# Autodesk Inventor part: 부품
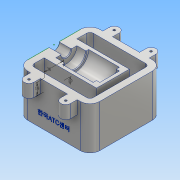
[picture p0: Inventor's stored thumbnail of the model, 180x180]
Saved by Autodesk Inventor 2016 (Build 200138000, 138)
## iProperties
Created: 2018-01
Part Number: 부품
Material: 알루미늄 6061
Document SubType Name: Modeling
Designer: Administrator
Density: 2.7 g/cm^3
Appearance: 알루미늄 - 평지
Mass: 1035.04 g
Surface Area: 788.468 cm^2
Volume: 383.348 cm^3
Author: Administrator
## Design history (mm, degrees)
sketch "스케치1"
  geometry: L1 (-55, 55)-(55, 55); L2 (55, 55)-(55, -55); L3 (55, -55)-(-55, -55); L4 (-55, -55)-(-55, 55); L5 (-55, 55)-(55, -55); L6 (55, 55)-(-55, -55); 1 further point
  constraints: 12 end point, 2 midpoint, 2 parallel, 1 horizontal, 1 perpendicular
  dimensions: "d0" = 110 distance of L1.start L1.end; "d1" = 110 distance of L1.end L2.end
extrude "돌출1" new body sketch "스케치1" distance "d2" = 65; taper "d3" = 0 deg
sketch "스케치2"
  geometry: L1 (55, 55)-(-55, 55) reference; L2 (-55, 55)-(-55, -55) reference; L3 (-55, -55)-(55, -55) reference; L4 (55, -55)-(55, 55) reference; L5 (-45, 45)-(-45, 25); L6 (-45, 25)-(35, 25); L7 (35, 25)-(35, -25); L8 (35, -25)-(-45, -25); L9 (-45, -25)-(-45, -45); L10 (-45, -45)-(45, -45); L11 (45, -45)-(45, 45); L12 (45, 45)-(-45, 45); 1 further point
  constraints: 16 end point, 6 perpendicular, 2 point on line, 1 vertical
  dimensions: "d4" = 30 distance between parallel lines of L1 L6; "d5" = 10 distance between parallel lines of L2 L5; "d6" = 20 distance between parallel lines of L4 L7; "d7" = 10 distance between parallel lines of L4 L11; "d8" = 10 distance between parallel lines of L1 L12; "d9" = 10 distance between parallel lines of L3 L10; "d10" = 30 distance between parallel lines of L3 L8
extrude "돌출2" cut sketch "스케치2" stored distance "d11" = 65; taper "d12" = 0 deg
sketch "스케치3"
  geometry: L1 (55, 55)-(-55, 55) reference; L2 (-55, 55)-(-55, -55) reference; L3 (-35.5, 65)-(-20.5, 65); L4 (-20.5, 65)-(-20.5, 55); L5 (-20.5, 55)-(-35.5, 55); L6 (-35.5, 55)-(-35.5, 65); L7 (-35.5, 65)-(-20.5, 55); L8 (-20.5, 65)-(-35.5, 55); L9 (0, 0)-(0, 92.754); L10 (20.5, 55)-(35.5, 55); L11 (35.5, 65)-(20.5, 65); L12 (20.5, 65)-(20.5, 55); L13 (35.5, 65)-(20.5, 55); L14 (20.5, 65)-(35.5, 55); L15 (35.5, 55)-(35.5, 65); A1 r 7.5 centre (-28, 65) between (-20.5, 65) and (-35.5, 65); A2 r 7.5 centre (28, 65) between (35.5, 65) and (20.5, 65); 2 further points
  constraints: 26 end point, 6 symmetric about line, 5 midpoint, 4 point on circle, 2 centre point, 2 parallel, 1 horizontal, 1 perpendicular, 1 point on line, 1 vertical, 1 other
  dimensions: "d13" = 27 distance from line of L2 A1.centre; "d14" = 7.5 radius of A1; "d15" = 10 distance between parallel lines of L1 L3
extrude "돌출3" join sketch "스케치3" distance "d16" = 20; taper "d17" = 0 deg
fillet "모깎기1" dims "d27" = 15
fillet "모깎기2" dims "d28" = 5
sketch "스케치8"
  geometry: L1 (45, -25)-(-35, -25); L2 (-35, -25)-(-35, 25); L3 (-35, 25)-(45, 25); L4 (45, 25)-(45, -25); 1 further point
  constraints: 8 end point, 2 parallel, 1 horizontal, 1 perpendicular
extrude "돌출4" cut sketch "스케치8" stored distance "d33" = 45; taper "d34" = 0 deg
sketch "스케치11"
  geometry: L1 (-55, -40)-(-55, 40) reference; L2 (-55, 25)-(35, 25); L3 (35, 25)-(35, -25); L4 (35, -25)-(-55, -25); L5 (-55, -25)-(-55, 25); 2 further points
  constraints: 8 end point, 2 parallel, 1 horizontal, 1 horizontal alignment, 1 midpoint, 1 perpendicular, 1 point on line
  dimensions: "d45" = 90 distance of L2.start L2.end; "d46" = 50 distance of L2.end L3.end
extrude "돌출5" join sketch "스케치11" stored distance "d47" = 40; taper "d48" = 0 deg
sketch "스케치12"
  geometry: L1 (-55, 40)-(-55, -40) reference; L2 (-55, 0)-(70.588, 0); L3 (-55, 0)-(-55, 7.5); L4 (-55, 7.5)-(-36, 7.5); L5 (-36, 7.5)-(-36, 16); L6 (-36, 16)-(-22, 16); L7 (-22, 16)-(-22, 20); L8 (-22, 20)-(25, 20); L9 (25, 20)-(25, 15); L10 (25, 15)-(30, 15); L11 (30, 15)-(30, 0); 1 further point
  constraints: 20 end point, 7 perpendicular, 2 horizontal, 2 point on line, 1 midpoint
  dimensions: "d49" = 15 diameter of L4 L2; "d50" = 19 distance of L3.end L4.end; "d51" = 14 distance of L5.end L6.end; "d52" = 32 diameter of L6 L2; "d53" = 40 diameter of L8 L2; "d54" = 30 diameter of L10 L2; "d55" = 47 distance of L7.end L8.end; "d56" = 5 distance of L9.end L10.end
revolve "회전2" sketch "스케치12" stored, may be unused: angle "d57" = 180 deg
sketch "스케치15"
  geometry: A1 r 7.5 centre (-28, -65) between (-35.5, -65) and (-20.5, -65) reference; A2 r 7.5 centre (28, -65) between (20.5, -65) and (35.5, -65) reference; A3 r 7.5 centre (28, 65) between (35.5, 65) and (20.5, 65) reference; A4 r 7.5 centre (-28, 65) between (-20.5, 65) and (-35.5, 65) reference; 5 further points
  constraints: 4 coincident
hole "구멍1" sketch "스케치15" at (-28, -65), (28, -65), (28, 65), (-28, 65) diameter "d66" = 3.242; stored, may be unused: countersink angle "d70" = 90 deg, drill point angle "d72" = 118 deg; dims "d67" = 9, "d68" = 4, "d69" = 2, "d71" = 11
sketch "스케치16" dims "d0" = 110, "d1" = 110
  geometry: L1 (60.5, -65)-(-19.5, -65) reference; L2 (-34.5, 0)-(-34.5, -65) reference; 2 further points
  constraints: 1 other
  dimensions: "d77" = 20 distance from line of L1 point (20.5, -45); "d78" = 55 distance from line of L2 point (20.5, -45)
feature "엠보싱1" sketch "스케치16" dims "d79" = 0.5, "d80" = 0
fillet "모깎기7" dims "d81" = 1
chamfer "모따기1" distance "d82" = 1; stored, may be unused: second distance "d83" = 2, angle "d84" = 45 deg
sketch "스케치19"
  geometry: L1 (-35, 65)-(-35, 0) reference; L2 (-35, 30)-(45, 8.564); L3 (45, 8.564)-(45, 0); L4 (40, 0)-(-40, 0) reference; L5 (55, 0)-(55, 65) reference; L6 (-35, 30)-(-35, 0); L7 (-32, 0)-(-32, 65) reference; L8 (45, 0)-(-35, 0); 1 further point
  constraints: 8 end point, 2 point on line, 1 collinear, 1 parallel, 1 vertical
  dimensions: "d85" = 105 deg angle of L3 L2; "d86" = 30 distance from line of L4 L2.start; "d87" = 10 distance between parallel lines of L5 L3
extrude "돌출7" cut sketch "스케치19" stored distance "d88" = 40; taper "d89" = 0 deg
sketch "스케치20"
  geometry: L1 (55, 0)-(55, 65) reference; L2 (55, 11.061)-(-20, 31.157); L3 (55, 29.061)-(17, 39.243); L4 (17, 39.243)-(17, 45); L5 (-24, 45)-(22, 45) reference; L6 (-35, 30)-(45, 8.564) reference; L7 (-20, 31.157)-(-20, 45); L8 (-25, 65)-(-25, 46) reference; 1 further point
  constraints: 8 end point, 4 point on line, 1 parallel, 1 perpendicular, 1 vertical
  dimensions: "d90" = 75 deg angle of L1 L3; "d92" = 5 distance between parallel lines of L6 L2; "d93" = 18 distance of L2.start L3.start; "d94" = 37 distance between parallel lines of L7 L4; "d95" = 5 distance between parallel lines of L8 L7
extrude "돌출8" join sketch "스케치20" stored distance "d96" = 18; taper "d97" = 0 deg
sketch "스케치21"
  geometry: L1 (65, 80)-(65, 48.5) reference; L2 (0, 80)-(65, 80) reference; L3 (0, 0)-(0, 80) reference; L4 (65, 0)-(0, 0) reference; L5 (65, 31.5)-(65, 0) reference; L6 (28, 55)-(10, 55); L7 (10, 55)-(10, 25); L8 (10, 25)-(28, 25); L9 (28, 25)-(28, 55); A1 r 8.5 centre (65, 40) between (65, 48.5) and (65, 31.5) reference; 2 further points
  constraints: 8 end point, 2 parallel, 1 horizontal, 1 horizontal alignment, 1 midpoint, 1 perpendicular
  dimensions: "d99" = 18 distance of L7.end L8.end; "d100" = 30 distance of L8.end L6.start; "d101" = 10 distance between parallel lines of L3 L7
node "솔리드1"
mirror "대칭1"
